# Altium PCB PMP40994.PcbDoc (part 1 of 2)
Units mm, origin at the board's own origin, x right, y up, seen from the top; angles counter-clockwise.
Board outline 46.72 x 34.79 mm, 2 copper layers (Top Layer, Bottom Layer), stack 1.575 mm thick; 64 components, 36 nets, 150 pads, 471 vias.
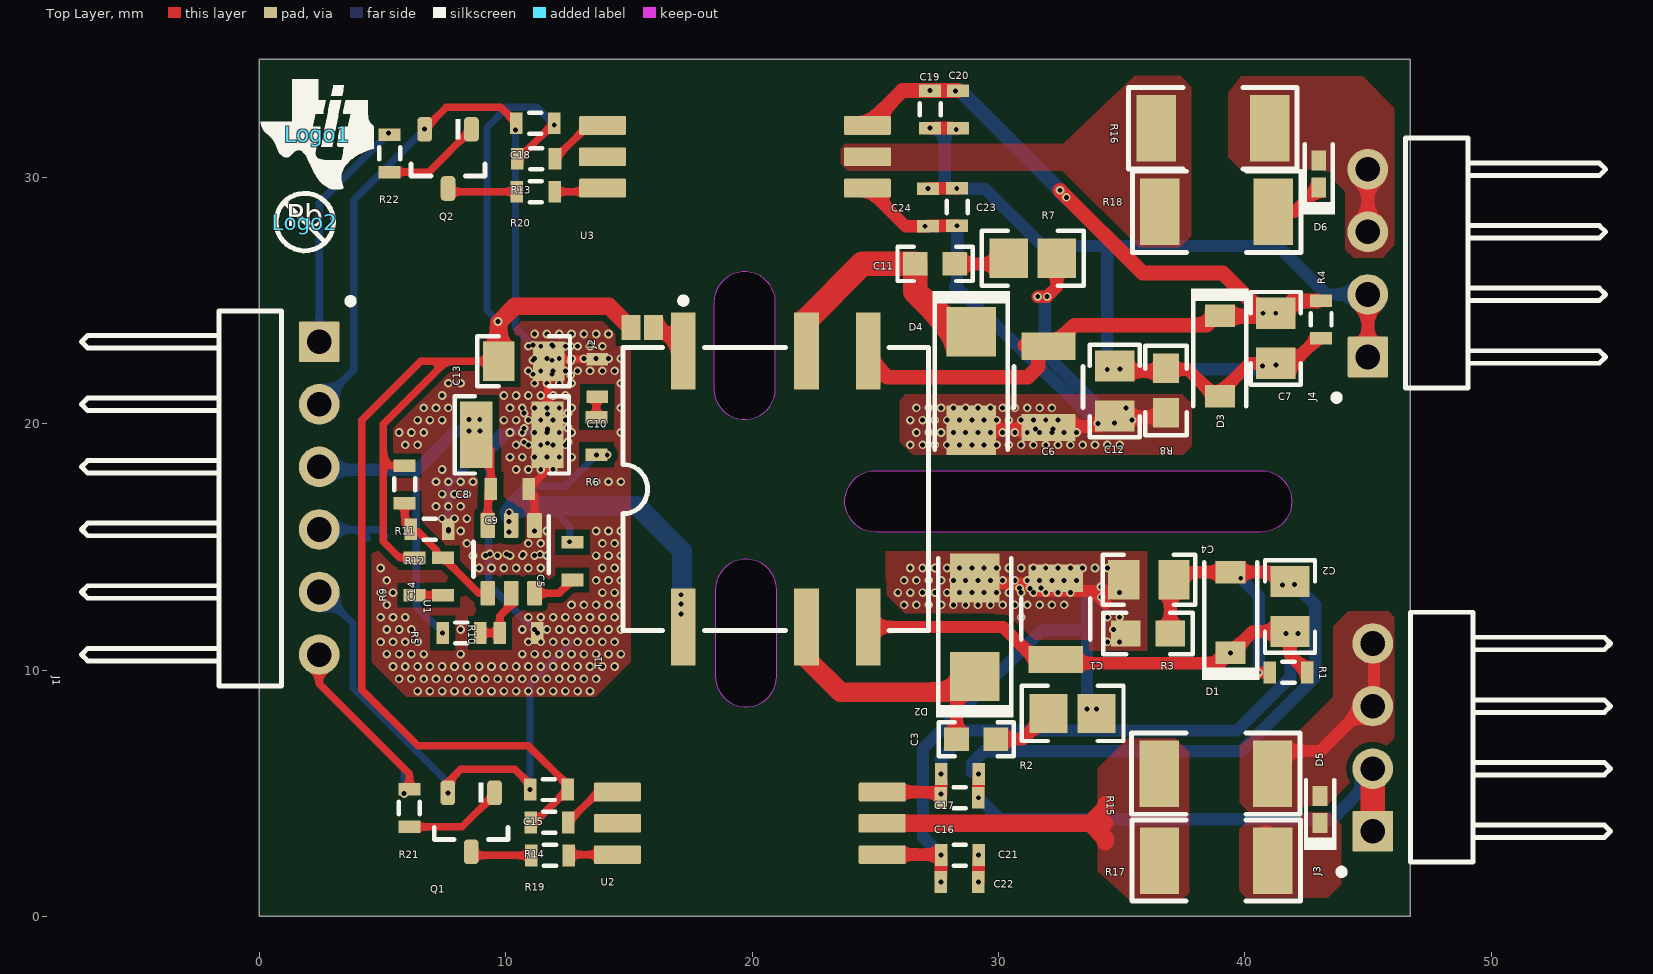
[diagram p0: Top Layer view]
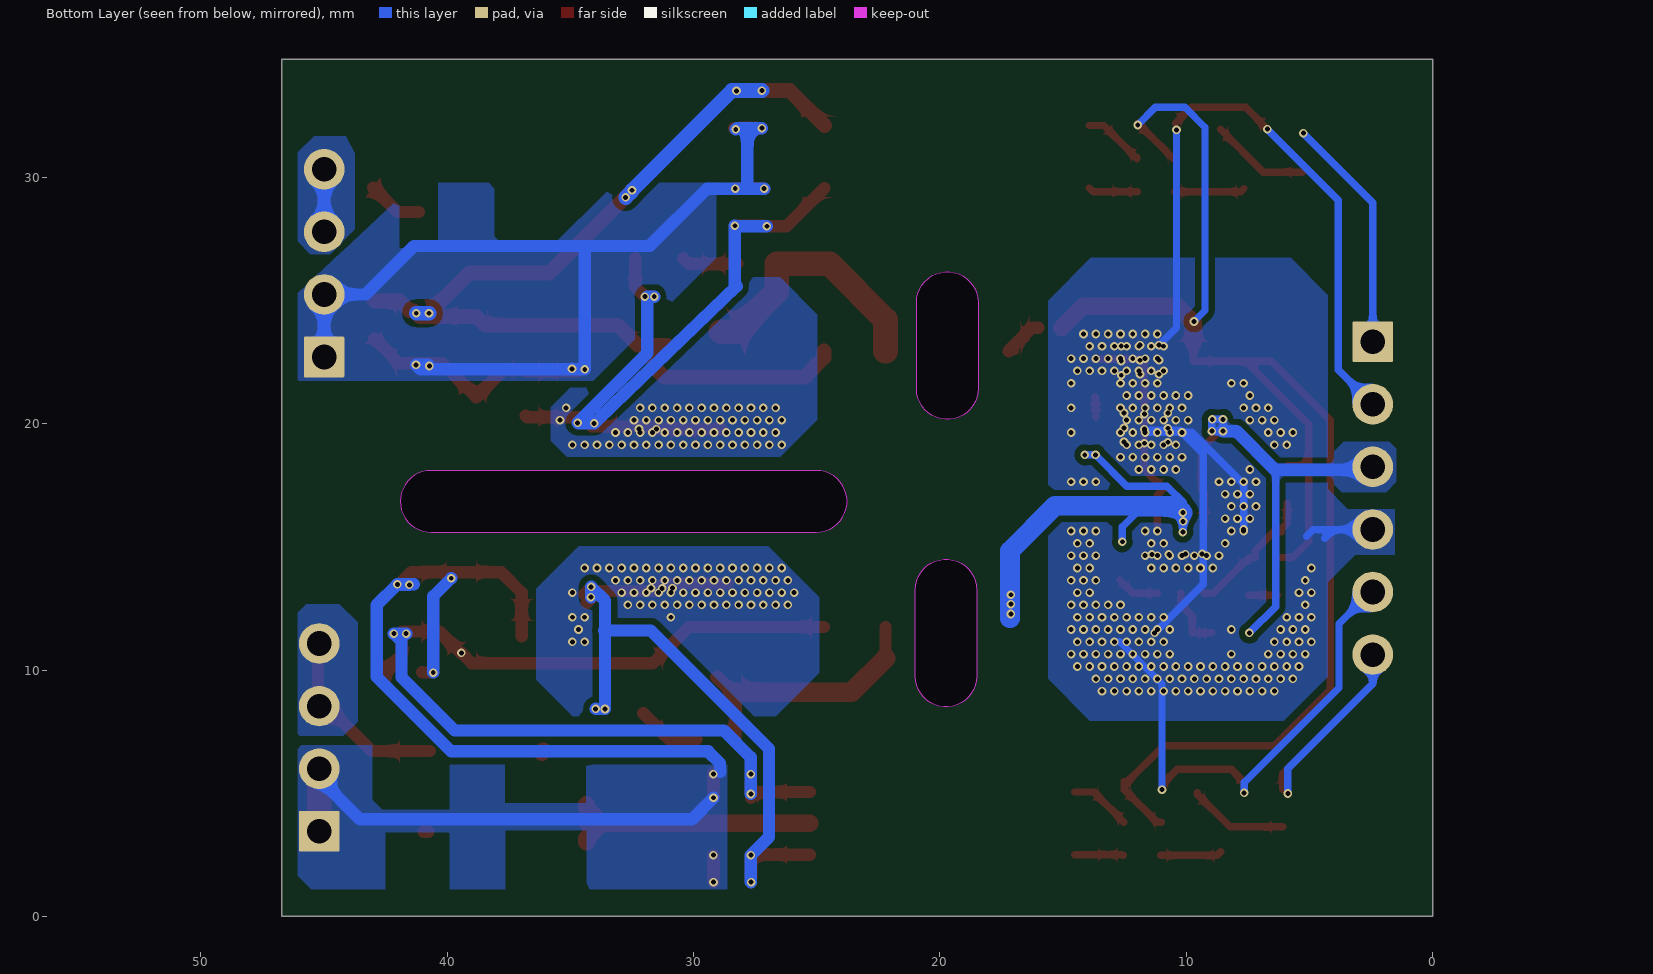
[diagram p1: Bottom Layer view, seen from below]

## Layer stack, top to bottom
Top Solder: solder mask 0.0102, Solder Resist, Dk 3.5
Top Layer: signal copper 0.0356
Dielectric1: core 1.5037, FR-4, Dk 4.8
Bottom Layer: signal copper 0.0356
Bottom Solder: solder mask 0.0102, Solder Resist, Dk 3.5

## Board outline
0,0 46.72,0 46.72,34.79 0,34.79
cut-out: 18.504,9.76 ccw(c19.755,9.76) 21.005,9.76 21.005,13.25 ccw(c19.755,13.25) 18.504,13.25
cut-out: 25.02,15.6 cw(c25.02,16.85) 25.02,18.1 40.66,18.1 cw(c40.66,16.85) 41.91,16.85 cw(c40.66,16.85) 40.66,15.6
cut-out: 18.45,21.43 ccw(c19.7,21.43) 20.95,21.43 20.95,24.92 ccw(c19.7,24.92) 18.45,24.92

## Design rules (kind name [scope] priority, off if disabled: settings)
AcuteAngle [All] p1: minimum=4.50000000000000E+0001 checktracksonly=FALSE
AssemblyTestPointUsage [All] p1: valid=2
BoardOutlineClearance BoardOutlineClearance_MountingHoles [OnCopper and InComponentClass('Mounting Holes')] p1: gap=1 ignorepadtopadclearanceinfootprint=FALSE
BoardOutlineClearance BoardOutlineClearance_Poly [OnCopper and IsPoly] p2: gap=0.635 ignorepadtopadclearanceinfootprint=FALSE
BoardOutlineClearance [OnCopper and Not InComponentClass('Logo') and not InComponentClass('FiducialMark') and not InRegion(1000,500,4000,800) and not InPoly] p3: gap=1 ignorepadtopadclearanceinfootprint=FALSE
Clearance Clearance_Keepouts [((IsTrack Or IsArc) And Not InPoly) And IsFree and IsKeepOut vs ((IsTrack Or IsArc) And Not InPoly) And IsFree and IsKeepOut] p1: gap=0 ignorepadtopadclearanceinfootprint=FALSE
Clearance Clearance_Poly [InPolygon] p2: gap=0.254 ignorepadtopadclearanceinfootprint=TRUE
Clearance Clearance_FiducialMark [IsKeepOut and InComponentClass('FiducialMark') vs IsPad and InComponentClass('FiducialMark')] p3: gap=0 ignorepadtopadclearanceinfootprint=FALSE
Clearance [All] p4: gap=0.2 ignorepadtopadclearanceinfootprint=TRUE
ComponentClearance ComponentClearance_MountingHoles_FiducialMarks [InComponentClass('Mounting Holes') vs InComponentClass('FiducialMark')] p1: gap=1.27 collisioncheckmode=3 verticalgap=0.254 showdistances=FALSE
ComponentClearance ComponentClearance_Shunt [InComponentClass('Header') vs InComponentClass('Shunt')] p2: gap=0 collisioncheckmode=3 verticalgap=0 showdistances=FALSE
ComponentClearance ComponentClearance_Logo [InComponentClass('Logo')] p3: gap=1.27 collisioncheckmode=3 verticalgap=0.254 showdistances=FALSE
ComponentClearance ComponentClearance_ScrewToNut [(HasFootprint('NY PMS 440 0025 PH')) vs (HasFootprint('Keystone_1902C'))] p4: gap=0.127 collisioncheckmode=3 verticalgap=0.254 showdistances=FALSE
ComponentClearance ComponentClearance_MountingHoles [InComponentClass('Mounting Holes')] p5: gap=6.35 collisioncheckmode=3 verticalgap=2540 showdistances=FALSE
ComponentClearance ComponentClearance_SmallPassives [HasFootprint('0201*') or HasFootprint('0402*') or HasFootprint('0508') or HasFootprint('0603*') or HasFootprint('0612') or HasFootprint('0805*') or HasFootprint('0815*') or HasFootprint('0830*') or HasFootprint('1206*') or HasFootprint('1210*') or HasFootprint('1808*') or HasFootprint('1812*') or HasFootprint('1825*') or HasFootprint('2010*') or HasFootprint('2220*') or HasFootprint('2225*') or HasFootprint('2512*') or HasFootprint('2728*') or HasFootprint('3518*') vs HasFootprint('0201*') or HasFootprint('0402*') or HasFootprint('0508') or HasFootprint('0603*') or HasFootprint('0612') or HasFootprint('0805*') or HasFootprint('0815*') or HasFootprint('0830*') or HasFootprint('1206*') or HasFootprint('1210*') or HasFootprint('1808*') or HasFootprint('1812*') or HasFootprint('1825*') or HasFootprint('2010*') or HasFootprint('2220*') or HasFootprint('2225*') or HasFootprint('2512*') or HasFootprint('2728*') or HasFootprint('3518*')] p6: gap=0.38 collisioncheckmode=3 verticalgap=0.254 showdistances=FALSE
ComponentClearance ComponentClearance_THtoSMT [IsThruComponent vs IsSMTComponent] p7: gap=1.016 collisioncheckmode=3 verticalgap=0.762 showdistances=FALSE
ComponentClearance ComponentClearance_THtoTH [IsThruComponent vs IsThruComponent] p8: gap=0.762 collisioncheckmode=3 verticalgap=0.508 showdistances=FALSE
ComponentClearance [All] p9: gap=0.762 collisioncheckmode=3 verticalgap=0.254 showdistances=FALSE
DiffPairsRouting [All] p1: maxlimit=2.54 minlimit=0.254 mostfreqgap=0.254 toplayer_minwidth=0.381 toplayer_maxwidth=0.381 toplayer_prefwidth=0.381 bottomlayer_minwidth=0.381 bottomlayer_maxwidth=0.381 bottomlayer_prefwidth=0.381 maxuncoupledlength=25.4
FabricationTestPointUsage TestPointUsage [All] p1: valid=2 allowmultiple=FALSE
FabricationTestpoint Testpoint [All] p1: side=3 testpointundercomponent=TRUE minsize=1.016 maxsize=2.54 preferedsize=1.524 minholesize=0 maxholesize=1.016 preferedholesize=0.813 testpointgrid=0.025 allowsidetop=TRUE allowsidebottom=TRUE usegrid=TRUE gridtolerance=0
FanoutControl Fanout_LCC [IsLCC] p1: bgadir=Out bgaviamode=Centered fanoutstyle=Auto fanoutdirection=Alternating viagrid=0.025 // Fanout_LCC (Default Rule)
FanoutControl Fanout_BGA [IsBGA] p2: bgadir=Out bgaviamode=Centered fanoutstyle=Auto fanoutdirection=Alternating viagrid=0.025 // Fanout_BGA (Default Rule)
FanoutControl Fanout_Default [All] p4: bgadir=Out bgaviamode=Centered fanoutstyle=Auto fanoutdirection=Alternating viagrid=0.025 // Fanout_Default (Default Rule)
FanoutControl Fanout_Small [(CompPinCount < 5)] p5: bgadir=Out bgaviamode=Centered fanoutstyle=Auto fanoutdirection=OutThenIn viagrid=0.025 // Fanout_Small (Default Rule)
HoleSize [All] p1: absolutevalues=TRUE maxlimit=6.375 minlimit=0.178 maxpercent=80.000 minpercent=20.000
MinimumAnnularRing MinimumAnnularRing_ThermalPadVias [IsVia and InAnyComponent] p1: minimumring=0.15
MinimumAnnularRing [All] p2: minimumring=0.2
MinimumSolderMaskSliver MinimumSolderMaskSliver_Logo [InComponentClass('Logo') vs InComponentClass('Logo')] p1: minsoldermaskwidth=0.018
MinimumSolderMaskSliver [All] p2: minsoldermaskwidth=0.1
PlaneClearance [All] p1: clearance=0.381
PlaneConnect [All] p1: planeconnectstyle=Direct reliefexpansion=0.254 reliefentries=4 reliefconductorwidth=0.254 reliefairgap=0.254
PolygonConnect [All] p1: connectstyle=Direct reliefconductorwidth=0.254 reliefentries=4 polygonreliefangle="90 Angle" airgapwidth=0.254
RoutingVias ThermalPadVias [IsVia and InAnyComponent] p1: holewidth=0.2 width=0.5 viastyle="Through Hole" minholewidth=0.2 minwidth=0.5 maxholewidth=0.33 maxwidth=0.6
RoutingVias [All] p2: holewidth=0.406 width=0.864 viastyle="Through Hole" minholewidth=0.2 minwidth=0.66 maxholewidth=1.016 maxwidth=1.651
SilkToBoardRegionClearance [Not ((IsComment or IsDesignator) And (Hide <> 'False')) and not InRegion(1000,500,4000,800)] p1:
SilkToSilkClearance SilkToSilkClearance_Pb-FreeLogo [(HasFootprint('Pb-Free_Overlay_Medium') OR HasFootprint('Pb-Free_Overlay_Small')) vs (HasFootprint('Pb-Free_Overlay_Medium') OR HasFootprint('Pb-Free_Overlay_Small'))] p1: silktosilkclearance=0
SilkToSilkClearance [All] p2: silktosilkclearance=0.1
SilkToSolderMaskClearance SilkToComponentPadClearance [(IsPad or IsFill or IsRegion) and InAnycomponent] p1: minsilkscreentomaskgap=0.127 clearancetoexposedcopper=TRUE
SilkToSolderMaskClearance "Silk to Solder Mask Opening" [All] p2: minsilkscreentomaskgap=0.1 clearancetoexposedcopper=FALSE
SolderMaskExpansion [All] p1: expansion=0.05
UnRoutedNet [All] p1: checkbadconnections=TRUE
Width [All] p1: maxlimit=2.54 minlimit=0.152 preferedwidth=0.5 checkconnectedcopper=TRUE
13 further rules are at their usual default settings.

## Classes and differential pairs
component class Hardware: !PCB Logo1

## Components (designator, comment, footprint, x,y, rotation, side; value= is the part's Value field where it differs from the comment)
C1 "C3225X7R1H106M250AC" 1210_280 32.33,12.08 r90 top value=10uF
C2 "GRM21BR61C226ME44L" 0805_HV 41.84,12.58 r270 top value=22uF
C3 "GRM1885C2A101JA01D" 0603 29.1,7.2 r180 top value=100pF
C4 "GRM21BR61C226ME44L" 0805_HV 36.11,13.67 r0 top value=22uF
C5 "C1608X7R1E104K080AA" 0603S 12.709,14.42 r270 top value=0.1uF
C6 "C3225X7R1H106M250AC" 1210_280 32.03,21.496 r270 top value=10uF
C7 "GRM21BR61C226ME44L" 0805_HV 41.26,23.47 r90 top value=22uF
C8 "GRM32ER7YA106KA12L" 1210 10.255,19.55 r180 top value=10uF
C9 "C1608X7R1E104K080AA" 0603S 10.165,17.35 r0 top value=0.1uF
C10 "GRM1885C2A101JA01D" 0603S 13.718,21.86 r90 top value=100pF
C11 "GRM1885C2A101JA01D" 0603 27.43,26.49 r180 top value=100pF
C12 "GRM21BR61C226ME44L" 0805_HV 34.72,21.329 r90 top value=22uF
C13 "GRM21BR61C226ME44L" 0805_HV 10.73,22.54 r180 top value=22uF
C14 "GRM1885C2A101JA01D" 0603S 7.46,13.8 r90 top value=100pF
C15 "C0603C104Z3VACTU" 0603S 11.75,5.15 r180 top value=0.1uF
C16 "C0603C104Z3VACTU" 0603S 28.43,4.82 r0 top value=0.1uF
C17 "GRM188C71E225KE11D" 0603S 28.44,5.78 r0 top value=2.2uF
C18 "C0603C104Z3VACTU" 0603S 11.2,32.2 r180 top value=0.1uF
C19 "C0603C104Z3VACTU" 0603S 27.23,32.763 r270 top value=0.1uF
C20 "GRM188C71E225KE11D" 0603S 28.364,32.763 r270 top value=2.2uF
C21 "C0603C104Z3VACTU" 0603S 28.438,2.49 r0 top value=0.1uF
C22 "GRM188C71E225KE11D" 0603S 28.43,1.392 r0 top value=2.2uF
C23 "C0603C104Z3VACTU" 0603S 28.329,28.8 r90 top value=0.1uF
C24 "GRM188C71E225KE11D" 0603S 27.139,28.781 r90 top value=2.2uF
D1 "BZT52C15-7-F" SOD-123 39.43,12.34 r90 top value=15V
D2 "BYS12-90HE3_A/I" SMA 29.04,11.74 r90 top value=90V
D3 "BZT52C15-7-F" SOD-123 38.99,22.75 r270 top value=15V
D4 "BYS12-90HE3_A/I" SMA 28.9,21.74 r270 top value=90V
D5 "NSR0240V2T1G" SOD-523 43.06,4.34 r90 top value=40V
D6 "NSR0240V2T1G" SOD-523 43.01,30.14 r90 top value=40V
J1 "TSW-106-08-G-S-RA" TSW-106-08-G-S-RA 2.43,16.98 r270 top
J2 "ShortingJumper" JMP-36-30X40SMT 15.54,23.9 r180 top
J3 "TSW-104-08-G-S-RA" TSW-104-08-G-S-RA 45.2,7.27 r90 top
J4 "TSW-104-08-G-S-RA" TSW-104-08-G-S-RA 45,26.52 r90 top
Logo1 "Texas Instruments" TI_Symbol_Overlay_Small 2.35,31.742 r0 top
Logo2 "Pb-Free Symbol" Pb-Free_Overlay_Small 1.845,28.19 r0 top
Q1 "2N7002" SOT-23 8.6,3.82 r270 top value=60V
Q2 "2N7002" SOT-23 7.66,30.75 r270 top value=60V
R1 "CRCW06035K11FKEA" 0603S 41.782,9.91 r0 top value=5.11k
R2 "RT0805BRD07100RL" 0805M 33.015,8.24 r0 top value=100
R3 "CRCW06033K30JNEA" 0603M 36.08,11.49 r0 top value=3.3k
R4 "CRCW06035K11FKEA" 0603S 43.1,24.24 r90 top value=5.11k
R5 "CRCW0603510KJNEA" 0603S 8.202,11.51 r180 top value=510k
R6 "RC0603FR-07100RL" 0603S 13.684,19.5 r270 top value=100
R7 "RT0805BRD07100RL" 0805M 31.395,26.72 r0 top value=100
R8 "CRCW06033K30JNEA" 0603M 36.81,21.35 r90 top value=3.3k
R9 "CRCW06032K26FKEA" 0603S 6.302,13.808 r90 top value=2.26k
R10 "CRCW060368K1FKEA" 0603S 10.525,11.51 r180 top value=68.1k
R11 "CRCW0603100KJNEA" 0603S 5.9,17.54 r90 top value=100k
R12 "CRCW060313K7FKEA" 0603S 6.912,15.718 r180 top value=13.7k
R13 "CRCW0603130RJNEA" 0603S 11.24,30.76 r180 top value=130
R14 "CRCW0603130RJNEA" 0603S 11.77,3.82 r180 top value=130
R15 "CRCW201010R0FKEF" 2010 38.83,5.8 r0 top value=10.0
R16 "CRCW201010R0FKEF" 2010 38.71,32 r0 top value=10.0
R17 "CRCW20104R70JNEF" 2010 38.84,2.27 r0 top value=4.7
R18 "CRCW20104R70JNEF" 2010 38.86,28.6 r0 top value=4.7
R19 "CRCW0603130RJNEA" 0603S 11.8,2.48 r0 top value=130
R20 "CRCW0603130RJNEA" 0603S 11.22,29.42 r0 top value=130
R21 "CRCW0603100RJNEA" 0603S 6.09,4.4 r90 top value=100
R22 "CRCW0603100RJNEA" 0603S 5.29,30.98 r90 top value=100
T1 "750345193" 750345193 20.963,17.35 r270 top locked value=10uH
U1 "TPS54308DDCR" DDC0006A_N 10.225,14.495 r270 top
U2 "UCC23513DWY" DWY0006A 19.91,3.78 r0 top
U3 "UCC23513DWY" DWY0006A 19.31,30.84 r0 top

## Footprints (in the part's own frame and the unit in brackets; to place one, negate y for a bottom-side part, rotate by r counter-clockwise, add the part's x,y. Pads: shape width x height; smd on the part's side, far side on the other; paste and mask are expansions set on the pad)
0603 [mm] "0603 from SM-752 data"
  rect 1x0.95 smd: 1(-0.8,0) 2(0.8,0)
  silkscreen extent -1.52,-0.69 1.52,0.69, body extent -0.87,-0.47 0.87,0.47, height 1
0603M [mm] "0603 from SM-752 data"
  rect 1.2x1.05 smd: 1(-0.9,0) 2(0.9,0)
  silkscreen extent -1.82,-0.84 1.82,0.84, body extent -0.87,-0.47 0.87,0.47, height 1
0603S [mil]
  rect 20x35 smd: 1(-30,0) 2(30,0)
  body extent -34,-19 34,19, height 39
0805_HV [mil] "0805 with 30mil clearance between pads"
  rect 50x63 smd: 1(-40,0) 2(40,0)
  silkscreen extent -74,-40 74,40, body extent -43,-29 43,29, height 57
0805M [mm] "0805 from SM-752 data"
  rect 1.55x1.6 smd: 1(-0.975,0) 2(0.975,0)
  silkscreen extent -2.07,-1.12 2.07,1.12, body extent -1.1,-0.72 1.1,0.72, height 1.45
1210 [mm] "1210 from SM-752 data"
  rect 1.3x2.7 smd: 1(-1.45,0) 2(1.45,0)
  silkscreen extent -2.32,-1.57 2.32,1.57, body extent -1.7,-1.35 1.7,1.35, height 1.35
1210_280 [mm] "SMD, 2-Leads, Body 3.6x2.8mm, Height 2.8mm"
  rect 1.1x2.2 smd: 1(-1.65,0) 2(1.65,0)
  silkscreen extent -0.84,-1.4 0.84,1.4, body extent -1.8,-1.4 1.8,1.4, height 2.8
2010 [mm] "Chip Capacitor, Body 5.08x2.54mm, IPC Medium Density"
  rect 1.6x2.7 smd: 1(-2.3,0) 2(2.3,0)
  silkscreen extent -3.42,-1.65 3.42,1.65, body extent -2.73,-1.45 2.73,1.45, height 1.66
750345193 [mm]
  rect 3.12x1 smd: 1(-5.6,-3.75) 3(-5.6,1.25) 4(-5.6,3.75) 5(5.6,3.75) 6(5.6,1.25) 8(5.6,-3.75)
  silkscreen extent -7.77,-6.2 5.75,6.2, body extent -6.6,-6.07 6.6,6.06, height 12.51
DDC0006A_N [mm]
  rrect17% 1x0.6 smd: 1(-1.375,0.95) 2(-1.375,0) 3(-1.375,-0.95) 4(1.375,-0.95) 5(1.375,0) 6(1.375,0.95)
  silkscreen extent -1.75,-1.52 0.7,1.53, body extent -1.43,-1.48 1.43,1.49, height 0.92
DWY0006A [mm] "SOIC-6"
  rrect13% 1.905x0.76 smd: 1(-5.375,1.27) 2(-5.375,0) 3(-5.375,-1.27) 4(5.375,-1.27) 5(5.375,0) 6(5.375,1.27)
  body extent -5.75,-2.34 5.75,2.34, height 3.38
JMP-36-30X40SMT [mil] "from PADS library"
  rect 30x40 smd mask+3: 1(-18,0) 2(18,0)
Pb-Free_Overlay_Small [mm]
  silkscreen extent -1.16,-1.17 1.17,1.17
SMA [mm] "Molded Diode, 2-Leads, Body 4.3x2.6mm, IPC Medium Density, based on OnSemi component dimensions and land pattern"
  rect 2x2 smd: 1(-2,0) 2(2,0)
  silkscreen extent -3.66,-1.57 2.79,1.57, body extent -2.6,-1.3 2.6,1.3, height 2.42
SOD-123 [mm] "On Semi recommended land pattern"
  rect 0.915x1.22 smd: 1(-1.637,0) 2(1.637,0)
  silkscreen extent -2.74,-1.17 2.03,1.17, body extent -1.93,-0.9 1.93,0.9, height 1.35
SOD-523 [mm] "NXP Semiconductor recommended land pattern, nominal STEP model"
  rect 0.8x0.6 smd paste-0.05: 1(-0.55,0) 2(0.55,0)
  silkscreen extent -1.65,-0.66 1.2,0.66, body extent -0.8,-0.4 0.8,0.4, height 0.72
SOT-23 [mm] "SOT23, 3-Leads, Body 2.9x1.3mm, Pitch 0.95mm, Lead Span 2.5mm, IPC Medium Density"
  rrect50% 1x0.6 smd: 1(-1.2,0.95) 2(-1.2,-0.95) 3(1.2,0)
  silkscreen extent -1.63,-1.5 0.7,1.5, body extent -1.16,-1.45 1.21,1.45, height 1
TI_Symbol_Overlay_Small [mm]
  silkscreen extent -2.3,-2.23 2.3,2.24
TSW-104-08-G-S-RA [mm] "Samtec Right Angle Header"
  rrect6% 1.65x1.65 hole 1: 1(-3.81,0)
  round 1.65 hole 1: 2(-1.27,0) 3(1.27,0) 4(3.81,0)
  silkscreen extent -5.58,-9.65 5.08,1.39, body extent -5.08,-9.91 5.08,0.32, height 3.05
TSW-106-08-G-S-RA [mm] "Samtec Right Angle Header"
  rrect6% 1.65x1.65 hole 1: 1(-6.35,0)
  round 1.65 hole 1: 2(-3.81,0) 3(-1.27,0) 4(1.27,0) 5(3.81,0) 6(6.35,0)
  silkscreen extent -8.12,-9.65 7.62,1.4, body extent -7.62,-9.91 7.62,0.32, height 3.05

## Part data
C1 C6: "CAP, CERM, 10 µF, 50 V, +/- 20%, X7R, 1210", Cap_Case=1210, Manufacturer=TDK, Supplier Part Number 1=445-14933-1-ND, TempCo=X7R, Tolerance_%=20, Value1=Unknown, Value2=50V, ValueDisplayed=10µF
C2 C4 C7 C12 C13: library part CMP-0008294-2, "CAP, CERM, 22 uF, 16 V, +/- 20%, X5R, 0805", Cap_Case=0805, Manufacturer=MuRata, Supplier Part Number 1=490-10747-1-ND, TempCo=X5R, Tolerance_%=20%, Value1=Unknown, Value2=16V, ValueDisplayed=22uF
C3 C10 C11 C14: library part CMP-0007237-3, "CAP, CERM, 100 pF, 100 V, +/- 5%, C0G/NP0, 0603", Cap_Case=0603, Manufacturer=MuRata, Supplier Part Number 1=490-1351-1-ND, TempCo=C0G/NP0, Tolerance_%=5%, Value1=Unknown, Value2=100V, ValueDisplayed=100pF
C5 C9: library part CMP-0007039-5, "CAP, CERM, 0.1 uF, 25 V, +/- 10%, X7R, 0603", Cap_Case=0603, Manufacturer=TDK, Supplier Part Number 1=445-1316-1-ND, TempCo=X7R, Tolerance_%=10%, Value1=Unknown, Value2=25V, ValueDisplayed=0.1uF
C8: "CAP, CERM, 10 µF, 35 V, +/- 10%, X7R, 1210", Cap_Case=1210, Manufacturer=MuRata, Supplier Part Number 1=490-5314-1-ND, TempCo=X7R, Tolerance_%=10, Value1=Unknown, Value2=35V, ValueDisplayed=10µF
C15 C16 C18 C19 C21 C23: library part CMP-0006865-1, "CAP, CERM, 0.1 uF, 25 V, +80/-20%, Y5V, 0603", Cap_Case=0603, Manufacturer=Kemet, Supplier Part Number 1=399-1100-1-ND, TempCo=Y5V, Tolerance_%=80%, Value1=Unknown, Value2=25V, ValueDisplayed=0.1uF
C17 C20 C22 C24: library part CMP-0075366-2, "CAP, CERM, 2.2 µF, 25 V,+/- 10%, X7S, 0603", Cap_Case=0603, Manufacturer=MuRata, Supplier Part Number 1=490-12732-1-ND, TempCo=X7S, Tolerance_%=10%, Value2=25V, ValueDisplayed=2.2µF
D1 D3: "Diode, Zener, 15 V, 370 mW, AEC-Q101, SOD-123", Manufacturer="Diodes Inc.", Power_W=0.37, Supplier Part Number 1=BZT52C15-FDICT-ND, Value1=0.37W
D2 D4: library part CMP-0028924-2, "Diode, Schottky, 90 V, 1 A, AEC-Q101, SMA", Manufacturer=Vishay-Semiconductor, PartNumber=MURA220T3G, Value1=1A, Value2=0.75V
D5 D6: "Diode, Schottky, 40 V, 0.25 A, SOD-523", Manufacturer="ON Semiconductor", Supplier Part Number 1=NSR0240V2T1GOSCT-ND, Value1=0.25A, Value2=0.7V
J1: "Header, 100mil, 6x1, Gold, R/A, TH", Color=Black, Current_A=6.3, Manufacturer=Samtec, Supplier Part Number 1=SAM1039-06-ND, Voltage_V=550
J2: library part CMP-0003883-1, "Jumper, SMT", Manufacturer=Any, PartNumber=JMP-36-30X40SMT
J3 J4: library part CMP-0055978-1, "Header, 100mil, 4x1, Gold, R/A, TH", Color=Black, Current_A=6.3A, Manufacturer=Samtec, Supplier Part Number 1=SAM1039-04-ND, Voltage_V=550V
Logo1: library part CMP-0074838-1, "Texas Instrument Corporate Signature"
Logo2: library part CMP-0074839-1
Q1 Q2: "MOSFET, N-CH, 60 V, 115 A, SOT-23", Alternate Manufacturer=None, Manufacturer="Fairchild Semiconductor", Supplier Part Number 1=2N7002NCT-ND, Value1="? ohm", Value2="? nC"
R1 R4: library part CMP-0022509-2, "RES, 5.11 k, 1%, 0.1 W, 0603", Manufacturer=Vishay-Dale, Power_W=100mW, Supplier Part Number 1=541-5.11KHCT-ND, TempCo="100 ppm/C", Tolerance_%=1%, Value2=0.1W, Value_Code=5k11, ValueDisplayed=5.11k
R2 R7: "RES, 100, 0.1%, 0.125 W, 0805", Manufacturer="Yageo America", Power_W=0.125, Supplier Part Number 1=YAG1760CT-ND, TempCo="25 ppm/C", Tolerance_%=0.1, Value1=0.1%, Value2=0.125W, Value_Code=100R, ValueDisplayed=100
R3 R8: "RES, 3.3 k, 5%, 0.1 W, 0603", Manufacturer=Vishay-Dale, Power_W=0.1, Supplier Part Number 1=541-3.3KGCT-ND, TempCo="200 ppm/C", Tolerance_%=5, Value1=5%, Value2=0.1W, Value_Code=3k30, ValueDisplayed=3.3k
R5: library part CMP-0025822-1, "RES, 510 k, 5%, 0.1 W, 0603", Manufacturer=Vishay-Dale, Power_W=100mW, Supplier Part Number 1=541-510KGCT-ND, TempCo="200 ppm/C", Tolerance_%=5%, Value2=0.1W, Value_Code=510k
R6: library part CMP-0022736-4, "RES, 100, 1%, 0.1 W, 0603", Manufacturer=Yageo, Power_W=100mW, Supplier Part Number 1=311-100HRCT-ND, TempCo="100 ppm/C", Tolerance_%=1%, Value2=0.1W, Value_Code=100R, ValueDisplayed=100
R9: library part CMP-0022273-3, "RES, 2.26 k, 1%, 0.1 W, 0603", Manufacturer=Vishay-Dale, Power_W=100mW, Supplier Part Number 1=541-2.26KHCT-ND, TempCo="100 ppm/C", Tolerance_%=1%, Value2=0.1W, Value_Code=2k26, ValueDisplayed=2.26k
R10: library part CMP-0022552-3, "RES, 68.1 k, 1%, 0.1 W, 0603", Manufacturer=Vishay-Dale, Power_W=100mW, Supplier Part Number 1=541-68.1KHCT-ND, TempCo="100 ppm/C", Tolerance_%=1%, Value2=0.1W, Value_Code=68k1, ValueDisplayed=68.1k
R11: library part CMP-0025698-1, "RES, 100 k, 5%, 0.1 W, 0603", Manufacturer=Vishay-Dale, Power_W=100mW, Supplier Part Number 1=541-100KGCT-ND, TempCo="200 ppm/C", Tolerance_%=5%, Value2=0.1W, Value_Code=100k
R12: library part CMP-0022044-1, "RES, 13.7 k, 1%, 0.1 W, 0603", Manufacturer=Vishay-Dale, Power_W=100mW, Supplier Part Number 1=541-13.7KHCT-ND, TempCo="100 ppm/C", Tolerance_%=1%, Value2=0.1W, Value_Code=13k7, ValueDisplayed=13.7k
R13 R14 R19 R20: library part CMP-0025714-1, "RES, 130, 5%, 0.1 W, 0603", Manufacturer=Vishay-Dale, Power_W=100mW, Supplier Part Number 1=541-130GCT-ND, TempCo="200 ppm/C", Tolerance_%=5%, Value2=0.1W, Value_Code=130R, ValueDisplayed=130
R15 R16: "RES, 10.0, 1%, 0.75 W, AEC-Q200 Grade 0, 2010", Manufacturer=Vishay-Dale, Power_W=0.75, Supplier Part Number 1=541-10.0ACCT-ND, TempCo="100 ppm/C", Tolerance_%=1, Value1=1%, Value2=0.75W, Value_Code=10R0, ValueDisplayed=10.0
R17 R18: "RES, 4.7, 5%, 0.75 W, AEC-Q200 Grade 0, 2010", Manufacturer=Vishay-Dale, Power_W=0.75, Supplier Part Number 1=541-4.7WCT-ND, TempCo="200 ppm/C", Tolerance_%=5, Value1=5%, Value2=0.75W, Value_Code=4R70, ValueDisplayed=4.7
R21 R22: "RES, 100, 5%, 0.1 W, 0603", Manufacturer=Vishay-Dale, Power_W=0.1, Supplier Part Number 1=541-100GCT-ND, TempCo="200 ppm/C", Tolerance_%=5, Value1=5%, Value2=0.1W, Value_Code=100R, ValueDisplayed=100
T1: "10uH EP10 Wurth", Manufacturer=Wurth, Operating Temperature Max=125°C, Operating Temperature Min=-40°C
U1: library part CMP-0013278-3, "4.5-V to 28-V Input, 3-A Output Synchronous Step-Down Converter, DDC0006A (SOT-6)", Alternate Manufacturer="Texas Instruments", Alternate PartNumber=TPS54308DDCT
U2 U3: library part CMP-0081091-2, "5-kVRMS, 3-A Single Channel Isolated Gate Driver with Opto Compatible Input, DWY0006A (SOIC-6)", Alternate Manufacturer="Texas Instruments", Alternate PartNumber=UCC23513DWYR

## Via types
v1: diameter 0.35, hole 0.2, Top Layer to Bottom Layer, 471 vias

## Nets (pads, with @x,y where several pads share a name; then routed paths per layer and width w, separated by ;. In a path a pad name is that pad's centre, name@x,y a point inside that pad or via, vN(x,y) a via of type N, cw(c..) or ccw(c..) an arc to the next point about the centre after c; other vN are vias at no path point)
+15V_A: C1.1 C2.2 C16.1 C17.1 D1.1 R1.2 T1.5 U2.6 | length 42.5
  Top Layer w0.5: T1.5@24.713,11.75 30.186,11.75 31.656,10.28 39.008,10.28 v1(39.43,10.703) 39.463,10.703 40.324,11.564 C2.2@41.84,11.564 41.84,10.614 R1.2@42.544,9.91 ; U2.6@25.285,5.05 27.438,5.05 C16.1@27.668,4.82 ; v1(27.68,4.97) C17.1@27.68,5.41
  Bottom Layer w0.5: v1(27.68,4.97) 27.68,6.46 28.77,7.55 39.7,7.55 41.86,9.71 41.86,11.17 v1(42.17,11.48) v1(41.67,11.48)
  other v1: 27.678,5.78
+15V_B: C6.1 C7.2 C19.1 C20.1 D3.1 R4.2 T1.4 U3.6 | length 44.1
  Top Layer w0.6: U3.6@24.685,32.11 26.1,33.525 v1(27.23,33.525) C20.1@28.364,33.525 ; T1.4@24.713,22.95 24.713,22.677 25.5,21.89 31.19,21.89 31.618,22.318 C6.1@31.618,23.19 ; C6.1@31.07,23.19 C6.1@31.618,23.19 ; v1(32.5,29.48) 35.86,26.12 39.11,26.12 v1(40.743,24.486) v1(41.26,24.486) ; R4.2@42.96,24.985 41.925,24.985 41.53,24.59 41.364,24.59 v1(41.26,24.486) ; C6.1@31.618,23.19 32.27,23.19 33.08,24 38.463,24 38.82,24.358 40.33,24.358 41.131,24.358 v1(41.26,24.486)
  Bottom Layer w0.6: v1(27.23,33.525) 28.455,33.525 v1(32.5,29.48) 32.5,29.45 v1(32.76,29.19) ; v1(40.743,24.486) v1(41.26,24.486)
  other v1: 28.261,33.513
-8V_A: C1.2 C4.1 C21.1 C22.1 D2.2 R2.2 R3.1 U2.4 | length 30.2
  Top Layer w0.5: U2.4@25.285,2.51 27.656,2.51 v1(27.676,2.49) 27.668,2.482 v1(27.668,1.392) ; D2.2@28.626,13.518 29.04,13.518 30.173,13.518 31.232,13.518 31.513,13.237 31.54,13.21 32.423,13.21 33.859,13.21 34.247,12.823 34.35,12.719 ; 34.274,13.24 34.44,13.074
  Bottom Layer w0.5: v1(27.668,1.392) 27.676,1.4 v1(27.676,2.49) 26.94,3.226 26.94,6.81 31.74,11.61 33.6,11.61 ; 33.63,11.61 33.6,11.61 ; v1(33.98,8.43) 33.97,8.42 v1(33.6,8.42) 33.6,11.61 ; v1(34.17,12.96) 34.17,13.37 v1(34.16,13.38) 33.6,12.82 33.6,11.61
  other v1: 34.423,11.146 34.923,11.146 34.673,11.646 30.923,12.146 34.423,12.146 34.923,12.146 26.173,12.646 26.673,12.646 27.173,12.646 27.673,12.646 28.173,12.646 28.673,12.646 29.173,12.646 29.673,12.646 30.173,12.646 30.673,12.646 31.173,12.646 31.673,12.646 32.173,12.646 32.673,12.646 25.923,13.146 26.423,13.146 26.923,13.146 27.423,13.146 27.923,13.146 28.423,13.146 28.923,13.146 29.423,13.146 29.923,13.146 30.423,13.146 30.923,13.146 31.423,13.146 31.923,13.146 32.423,13.146 32.923,13.146 34.923,13.146 31.28,13.32 30.86,13.33 31.73,13.33 26.173,13.646 26.673,13.646 27.173,13.646 27.673,13.646 28.173,13.646 28.673,13.646 29.173,13.646 29.673,13.646 30.173,13.646 30.673,13.646 31.173,13.646 31.673,13.646 32.173,13.646 32.673,13.646 33.173,13.646 26.423,14.146 26.923,14.146 27.423,14.146 27.923,14.146 28.423,14.146 28.923,14.146 29.423,14.146 29.923,14.146 30.423,14.146 30.923,14.146 31.423,14.146 31.923,14.146 32.423,14.146 32.923,14.146 33.423,14.146 33.923,14.146 34.423,14.146
-8V_B: C6.2 C12.1 C23.1 C24.1 D4.2 R7.2 R8.1 U3.4 | length 33.7
  Top Layer w0.5: U3.4@24.685,29.57 26.236,28.019 v1(27.03,28.019) C24.1@27.139,28.019 27.158,28.038 v1(28.329,28.038) ; D4.2@28.86,19.783 v1(31.51,19.783) 31.618,19.89 34.132,19.89 34.51,20.268 36.765,20.268 R8.1@36.817,20.32 ; v1(31.6,25.16) v1(31.98,25.16) 32.37,25.55 R7.2@32.37,26.72
  Bottom Layer w0.5: v1(27.03,28.019) 28.31,28.019 v1(28.329,28.038) 28.329,25.669 28.247,25.587 33.276,20.754 33.536,20.504 33.656,20.389 33.916,20.139 v1(34.04,20.02) 34.69,20.02 v1(34.71,20.04) 31.88,22.87 31.88,25.16 v1(31.6,25.16)
  other v1: 26.423,19.146 26.923,19.146 27.423,19.146 27.923,19.146 28.423,19.146 28.923,19.146 29.423,19.146 29.923,19.146 30.423,19.146 30.923,19.146 31.423,19.146 31.923,19.146 32.423,19.146 32.923,19.146 33.423,19.146 33.923,19.146 34.423,19.146 34.923,19.146 26.673,19.646 27.173,19.646 27.673,19.646 28.173,19.646 28.673,19.646 29.173,19.646 29.673,19.646 30.173,19.646 30.673,19.646 31.173,19.646 31.673,19.646 32.173,19.646 32.673,19.646 33.173,19.646 32.22,19.79 26.423,20.146 26.923,20.146 27.423,20.146 27.923,20.146 28.423,20.146 28.923,20.146 29.423,20.146 29.923,20.146 30.423,20.146 30.923,20.146 31.423,20.146 31.923,20.146 32.423,20.146 35.423,20.146 26.673,20.646 27.173,20.646 27.673,20.646 28.173,20.646 28.673,20.646 29.173,20.646 29.673,20.646 30.173,20.646 30.673,20.646 31.173,20.646 31.673,20.646 32.173,20.646 35.173,20.646
BOOT: C5.2 U1.6 | length 1.8
  Top Layer w0.3: U1.6@11.175,13.12 12.171,13.12 C5.2@12.709,13.658
EN: R5.1 R10.2 U1.5 | length 2.6
  Top Layer w0.3: R5.1@8.964,11.51 R10.2@9.763,11.51 9.763,12.193 10.225,12.655 U1.5@10.225,13.12
GateA: D5.2 J3.3 J3.4 R15.2 | length 7.9
  Top Layer w0.5: R15.2@40.71,6.72 43.08,6.72 45.25,8.89 J3.4@45.25,11.31
GateB: D6.2 J4.3 J4.4 R16.2 | length 5.2
  Top Layer w0.5: J4.3@45,27.79 J4.4@45,30.25 ; J4.4@45,30.25 44.96,30.29 J4.4@45,30.33 J4.4@45,30.25
  Bottom Layer w0.5: J4.3@45,27.79 J4.4@45,30.33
